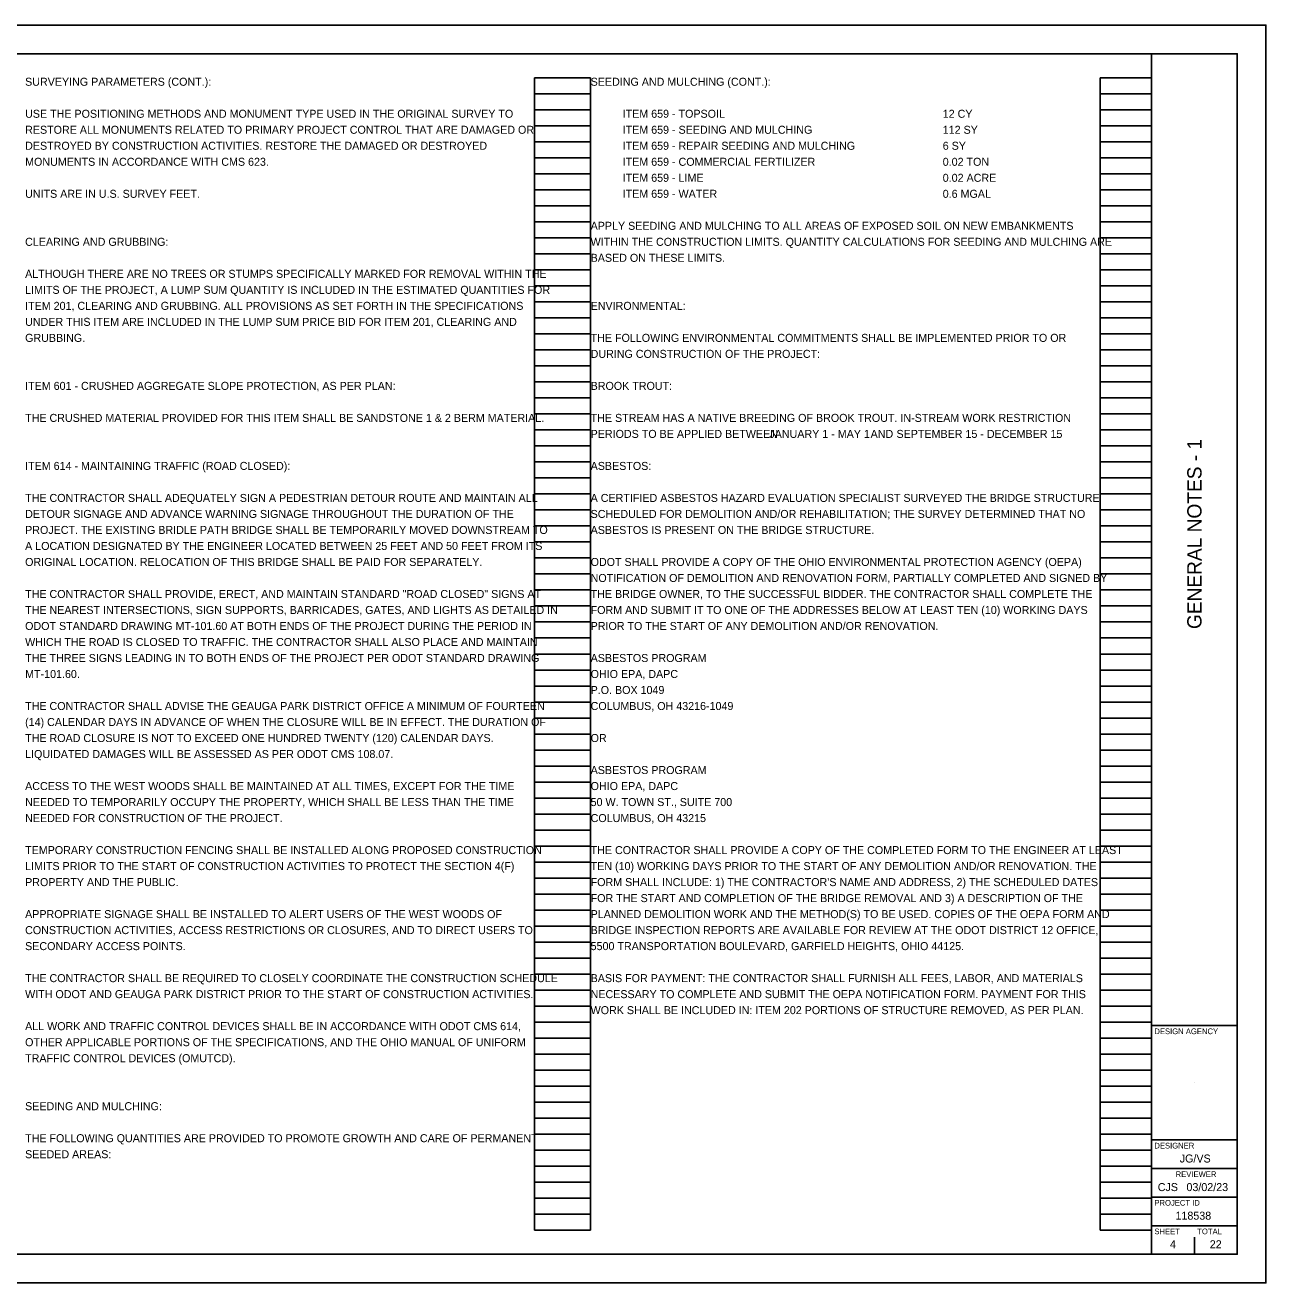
# Model space of a CAD drawing. Extents: x 0 to 34, y -0.1 to 22.
# Drawn here: x 12.29 to 34, y 0 to 22 of the extents above; entities that cross this region are included whole.
import ezdxf

# ---------------------------------------------------------------- set-up
doc = ezdxf.new("R2010")
doc.units = 0
for name, color, linetype in [('SH_Border', 7, 'Continuous'), ('SH_Cut_Line', 7, 'Continuous'), ('SH_Data', 7, 'Continuous'), ('SH_Text', 7, 'Continuous')]:
    doc.layers.add(name, color=color, linetype=linetype)

msp = doc.modelspace()

# ---------------------------------------------------------------- linework, layer by layer
at = {"layer": 'SH_Border'}
for p, q in [((32, 0.5), (32, 21.5)), ((32, 4.5), (33.5, 4.5)), ((32, 2.5), (33.5, 2.5)), ((32, 2), (33.5, 2)), ((32, 1.5), (33.5, 1.5)), ((32, 1), (33.5, 1))]:
    msp.add_line(p, q, dxfattribs=at)
msp.add_lwpolyline([(1.5, 21.5), (33.5, 21.5), (33.5, 0.5), (1.5, 0.5)], close=True, dxfattribs=at)
at = {"layer": 'SH_Cut_Line'}
msp.add_lwpolyline([(0, 0), (34, 0), (34, 22), (0, 22)], close=True, dxfattribs=at)
at = {"layer": 'SH_Data'}
for p, q in [((21.207, 0.92), (21.207, 21.08)), ((21.207, 21.08), (22.187, 21.08)), ((22.187, 0.92), (22.187, 21.08)), ((31.1, 0.92), (31.1, 21.08)), ((31.1, 21.08), (32, 21.08)), ((32, 0.92), (32, 21.08)), ((21.207, 20.8), (22.187, 20.8)), ((31.1, 20.8), (32, 20.8)), ((21.207, 20.52), (22.187, 20.52)), ((31.1, 20.52), (32, 20.52)), ((21.207, 20.24), (22.187, 20.24)), ((31.1, 20.24), (32, 20.24)), ((21.207, 19.96), (22.187, 19.96)), ((31.1, 19.96), (32, 19.96)), ((21.207, 19.68), (22.187, 19.68)), ((31.1, 19.68), (32, 19.68)), ((21.207, 19.4), (22.187, 19.4)), ((31.1, 19.4), (32, 19.4)), ((21.207, 19.12), (22.187, 19.12)), ((31.1, 19.12), (32, 19.12)), ((21.207, 18.84), (22.187, 18.84)), ((31.1, 18.84), (32, 18.84)), ((21.207, 18.56), (22.187, 18.56)), ((31.1, 18.56), (32, 18.56)), ((21.207, 18.28), (22.187, 18.28)), ((31.1, 18.28), (32, 18.28)), ((21.207, 18), (22.187, 18)), ((31.1, 18), (32, 18)), ((21.207, 17.72), (22.187, 17.72)), ((31.1, 17.72), (32, 17.72)), ((21.207, 17.44), (22.187, 17.44)), ((31.1, 17.44), (32, 17.44)), ((21.207, 17.16), (22.187, 17.16)), ((31.1, 17.16), (32, 17.16)), ((21.207, 16.88), (22.187, 16.88)), ((31.1, 16.88), (32, 16.88)), ((21.207, 16.6), (22.187, 16.6)), ((31.1, 16.6), (32, 16.6)), ((21.207, 16.32), (22.187, 16.32)), ((31.1, 16.32), (32, 16.32)), ((21.207, 16.04), (22.187, 16.04)), ((31.1, 16.04), (32, 16.04)), ((21.207, 15.76), (22.187, 15.76)), ((31.1, 15.76), (32, 15.76)), ((21.207, 15.48), (22.187, 15.48)), ((31.1, 15.48), (32, 15.48)), ((21.207, 15.2), (22.187, 15.2)), ((31.1, 15.2), (32, 15.2)), ((21.207, 14.92), (22.187, 14.92)), ((31.1, 14.92), (32, 14.92)), ((21.207, 14.64), (22.187, 14.64)), ((31.1, 14.64), (32, 14.64)), ((21.207, 14.36), (22.187, 14.36)), ((31.1, 14.36), (32, 14.36)), ((21.207, 14.08), (22.187, 14.08)), ((31.1, 14.08), (32, 14.08)), ((21.207, 13.8), (22.187, 13.8)), ((31.1, 13.8), (32, 13.8)), ((21.207, 13.52), (22.187, 13.52)), ((31.1, 13.52), (32, 13.52)), ((21.207, 13.24), (22.187, 13.24)), ((31.1, 13.24), (32, 13.24)), ((21.207, 12.96), (22.187, 12.96)), ((31.1, 12.96), (32, 12.96)), ((21.207, 12.68), (22.187, 12.68)), ((31.1, 12.68), (32, 12.68)), ((21.207, 12.4), (22.187, 12.4)), ((31.1, 12.4), (32, 12.4)), ((21.207, 12.12), (22.187, 12.12)), ((31.1, 12.12), (32, 12.12)), ((21.207, 11.84), (22.187, 11.84)), ((31.1, 11.84), (32, 11.84)), ((21.207, 11.56), (22.187, 11.56)), ((31.1, 11.56), (32, 11.56)), ((21.207, 11.28), (22.187, 11.28)), ((31.1, 11.28), (32, 11.28)), ((21.207, 11), (22.187, 11)), ((31.1, 11), (32, 11)), ((21.207, 10.72), (22.187, 10.72)), ((31.1, 10.72), (32, 10.72)), ((21.207, 10.44), (22.187, 10.44)), ((31.1, 10.44), (32, 10.44)), ((21.207, 10.16), (22.187, 10.16)), ((31.1, 10.16), (32, 10.16)), ((21.207, 9.88), (22.187, 9.88)), ((31.1, 9.88), (32, 9.88)), ((21.207, 9.6), (22.187, 9.6)), ((31.1, 9.6), (32, 9.6)), ((21.207, 9.32), (22.187, 9.32)), ((31.1, 9.32), (32, 9.32)), ((21.207, 9.04), (22.187, 9.04)), ((31.1, 9.04), (32, 9.04)), ((21.207, 8.76), (22.187, 8.76)), ((31.1, 8.76), (32, 8.76)), ((21.207, 8.48), (22.187, 8.48)), ((31.1, 8.48), (32, 8.48)), ((21.207, 8.2), (22.187, 8.2)), ((31.1, 8.2), (32, 8.2)), ((21.207, 7.92), (22.187, 7.92)), ((31.1, 7.92), (32, 7.92)), ((21.207, 7.64), (22.187, 7.64)), ((31.1, 7.64), (32, 7.64)), ((21.207, 7.36), (22.187, 7.36)), ((31.1, 7.36), (32, 7.36)), ((21.207, 7.08), (22.187, 7.08)), ((31.1, 7.08), (32, 7.08)), ((21.207, 6.8), (22.187, 6.8)), ((31.1, 6.8), (32, 6.8)), ((21.207, 6.52), (22.187, 6.52)), ((31.1, 6.52), (32, 6.52)), ((21.207, 6.24), (22.187, 6.24)), ((31.1, 6.24), (32, 6.24)), ((21.207, 5.96), (22.187, 5.96)), ((31.1, 5.96), (32, 5.96)), ((21.207, 5.68), (22.187, 5.68)), ((31.1, 5.68), (32, 5.68)), ((21.207, 5.4), (22.187, 5.4)), ((31.1, 5.4), (32, 5.4)), ((21.207, 5.12), (22.187, 5.12)), ((31.1, 5.12), (32, 5.12)), ((21.207, 4.84), (22.187, 4.84)), ((31.1, 4.84), (32, 4.84)), ((21.207, 4.56), (22.187, 4.56)), ((31.1, 4.56), (32, 4.56)), ((21.207, 4.28), (22.187, 4.28)), ((31.1, 4.28), (32, 4.28)), ((21.207, 4), (22.187, 4)), ((31.1, 4), (32, 4)), ((21.207, 3.72), (22.187, 3.72)), ((31.1, 3.72), (32, 3.72)), ((21.207, 3.44), (22.187, 3.44)), ((31.1, 3.44), (32, 3.44)), ((32.75, 3.5), (32.75, 3.5)), ((21.207, 3.16), (22.187, 3.16)), ((31.1, 3.16), (32, 3.16)), ((21.207, 2.88), (22.187, 2.88)), ((31.1, 2.88), (32, 2.88)), ((21.207, 2.6), (22.187, 2.6)), ((31.1, 2.6), (32, 2.6)), ((21.207, 2.32), (22.187, 2.32)), ((31.1, 2.32), (32, 2.32)), ((21.207, 2.04), (22.187, 2.04)), ((31.1, 2.04), (32, 2.04)), ((21.207, 1.76), (22.187, 1.76)), ((31.1, 1.76), (32, 1.76)), ((21.207, 1.48), (22.187, 1.48)), ((31.1, 1.48), (32, 1.48)), ((21.207, 1.2), (22.187, 1.2)), ((31.1, 1.2), (32, 1.2)), ((21.207, 0.92), (22.187, 0.92)), ((31.1, 0.92), (32, 0.92)), ((32.375, 0.675), (32.375, 0.675)), ((32.75, 0.5), (32.75, 0.8))]:
    msp.add_line(p, q, dxfattribs=at)

# ---------------------------------------------------------------- texts
msp.add_text('GENERAL NOTES - 1', height=0.25, rotation=90, dxfattribs=at).set_placement((32.875, 11.437))
for s, height, p in [('DESIGN AGENCY', 0.1, (32.05, 4.35)), ('DESIGNER', 0.1, (32.05, 2.35)), ('JG/VS', 0.14, (32.494, 2.105)), ('REVIEWER', 0.1, (32.422, 1.85)), ('CJS', 0.14, (32.109, 1.605)), ('03/02/23', 0.14, (32.611, 1.605)), ('PROJECT ID', 0.1, (32.05, 1.35)), ('118538', 0.14, (32.419, 1.105)), ('SHEET', 0.1, (32.05, 0.85)), ('TOTAL', 0.1, (32.8, 0.85)), ('4', 0.14, (32.322, 0.605)), ('22', 0.14, (33.019, 0.605))]:
    msp.add_text(s, height=height, dxfattribs=at).set_placement(p)
at = {"layer": 'SH_Text'}
for s, p in [('SURVEYING PARAMETERS (CONT.):', (12.293, 20.94)), ('SEEDING AND MULCHING (CONT.):', (22.187, 20.94)), ('USE THE POSITIONING METHODS AND MONUMENT TYPE USED IN THE ORIGINAL SURVEY TO ', (12.293, 20.38)), ('ITEM 659 - TOPSOIL', (22.747, 20.38)), ('12 CY', (28.347, 20.38)), ('RESTORE ALL MONUMENTS RELATED TO PRIMARY PROJECT CONTROL THAT ARE DAMAGED OR', (12.293, 20.1)), ('ITEM 659 - SEEDING AND MULCHING', (22.747, 20.1)), ('112 SY', (28.347, 20.1)), ('DESTROYED BY CONSTRUCTION ACTIVITIES. RESTORE THE DAMAGED OR DESTROYED ', (12.293, 19.82)), ('ITEM 659 - REPAIR SEEDING AND MULCHING', (22.747, 19.82)), ('6 SY', (28.347, 19.82)), ('MONUMENTS IN ACCORDANCE WITH CMS 623.', (12.293, 19.54)), ('ITEM 659 - COMMERCIAL FERTILIZER', (22.747, 19.54)), ('0.02 TON', (28.347, 19.54)), ('ITEM 659 - LIME', (22.747, 19.26)), ('0.02 ACRE', (28.347, 19.26)), ('UNITS ARE IN U.S. SURVEY FEET.', (12.293, 18.98)), ('ITEM 659 - WATER', (22.747, 18.98)), ('0.6 MGAL', (28.347, 18.98)), ('APPLY SEEDING AND MULCHING TO ALL AREAS OF EXPOSED SOIL ON NEW EMBANKMENTS ', (22.187, 18.42)), ('CLEARING AND GRUBBING:', (12.293, 18.14)), ('WITHIN THE CONSTRUCTION LIMITS. QUANTITY CALCULATIONS FOR SEEDING AND MULCHING ARE ', (22.187, 18.14)), ('BASED ON THESE LIMITS.', (22.187, 17.86)), ('ALTHOUGH THERE ARE NO TREES OR STUMPS SPECIFICALLY MARKED FOR REMOVAL WITHIN THE ', (12.293, 17.58)), ('LIMITS OF THE PROJECT, A LUMP SUM QUANTITY IS INCLUDED IN THE ESTIMATED QUANTITIES FOR ', (12.293, 17.3)), ('ITEM 201, CLEARING AND GRUBBING. ALL PROVISIONS AS SET FORTH IN THE SPECIFICATIONS ', (12.293, 17.02)), ('ENVIRONMENTAL:', (22.187, 17.02)), ('UNDER THIS ITEM ARE INCLUDED IN THE LUMP SUM PRICE BID FOR ITEM 201, CLEARING AND ', (12.293, 16.74)), ('GRUBBING.', (12.293, 16.46)), ('THE FOLLOWING ENVIRONMENTAL COMMITMENTS SHALL BE IMPLEMENTED PRIOR TO OR ', (22.187, 16.46)), ('DURING CONSTRUCTION OF THE PROJECT:', (22.187, 16.18)), ('ITEM 601 - CRUSHED AGGREGATE SLOPE PROTECTION, AS PER PLAN:', (12.293, 15.62)), ('BROOK TROUT:', (22.187, 15.62)), ('THE CRUSHED MATERIAL PROVIDED FOR THIS ITEM SHALL BE SANDSTONE 1 & 2 BERM MATERIAL.', (12.293, 15.06)), ('THE STREAM HAS A NATIVE BREEDING OF BROOK TROUT. IN-STREAM WORK RESTRICTION ', (22.187, 15.06)), ('PERIODS TO BE APPLIED BETWEEN ', (22.187, 14.78)), ('JANUARY 1 - MAY 1', (25.314, 14.78)), (' AND ', (27.033, 14.78)), ('SEPTEMBER 15 - DECEMBER 15', (27.538, 14.78)), ('.', (30.322, 14.78)), ('ITEM 614 - MAINTAINING TRAFFIC (ROAD CLOSED):', (12.293, 14.22)), ('ASBESTOS:', (22.187, 14.22)), ('THE CONTRACTOR SHALL ADEQUATELY SIGN A PEDESTRIAN DETOUR ROUTE AND MAINTAIN ALL ', (12.293, 13.66)), ('A CERTIFIED ASBESTOS HAZARD EVALUATION SPECIALIST SURVEYED THE BRIDGE STRUCTURE ', (22.187, 13.66)), ('DETOUR SIGNAGE AND ADVANCE WARNING SIGNAGE THROUGHOUT THE DURATION OF THE ', (12.293, 13.38)), ('SCHEDULED FOR DEMOLITION AND/OR REHABILITATION; THE SURVEY DETERMINED THAT NO ', (22.187, 13.38)), ('PROJECT. THE EXISTING BRIDLE PATH BRIDGE SHALL BE TEMPORARILY MOVED DOWNSTREAM TO ', (12.293, 13.1)), ('ASBESTOS IS PRESENT ON THE BRIDGE STRUCTURE.', (22.187, 13.1)), ('A LOCATION DESIGNATED BY THE ENGINEER LOCATED BETWEEN 25 FEET AND 50 FEET FROM ITS ', (12.293, 12.82)), ('ORIGINAL LOCATION. RELOCATION OF THIS BRIDGE SHALL BE PAID FOR SEPARATELY.', (12.293, 12.54)), ('ODOT SHALL PROVIDE A COPY OF THE OHIO ENVIRONMENTAL PROTECTION AGENCY (OEPA) ', (22.187, 12.54)), ('NOTIFICATION OF DEMOLITION AND RENOVATION FORM, PARTIALLY COMPLETED AND SIGNED BY ', (22.187, 12.26)), ('THE CONTRACTOR SHALL PROVIDE, ERECT, AND MAINTAIN STANDARD "ROAD CLOSED" SIGNS AT ', (12.293, 11.98)), ('THE BRIDGE OWNER, TO THE SUCCESSFUL BIDDER. THE CONTRACTOR SHALL COMPLETE THE ', (22.187, 11.98)), ('THE NEAREST INTERSECTIONS, SIGN SUPPORTS, BARRICADES, GATES, AND LIGHTS AS DETAILED IN ', (12.293, 11.7)), ('FORM AND SUBMIT IT TO ONE OF THE ADDRESSES BELOW AT LEAST TEN (10) WORKING DAYS ', (22.187, 11.7)), ('ODOT STANDARD DRAWING MT-101.60 AT BOTH ENDS OF THE PROJECT DURING THE PERIOD IN ', (12.293, 11.42)), ('PRIOR TO THE START OF ANY DEMOLITION AND/OR RENOVATION.', (22.187, 11.42)), ('WHICH THE ROAD IS CLOSED TO TRAFFIC. THE CONTRACTOR SHALL ALSO PLACE AND MAINTAIN ', (12.293, 11.14)), ('THE THREE SIGNS LEADING IN TO BOTH ENDS OF THE PROJECT PER ODOT STANDARD DRAWING ', (12.293, 10.86)), ('ASBESTOS PROGRAM', (22.187, 10.86)), ('MT-101.60.', (12.293, 10.58)), ('OHIO EPA, DAPC', (22.187, 10.58)), ('P.O. BOX 1049', (22.187, 10.3)), ('THE CONTRACTOR SHALL ADVISE THE GEAUGA PARK DISTRICT OFFICE A MINIMUM OF FOURTEEN ', (12.293, 10.02)), ('COLUMBUS, OH 43216-1049', (22.187, 10.02)), ('(14) CALENDAR DAYS IN ADVANCE OF WHEN THE CLOSURE WILL BE IN EFFECT. THE DURATION OF ', (12.293, 9.74)), ('THE ROAD CLOSURE IS NOT TO EXCEED ONE HUNDRED TWENTY (120) CALENDAR DAYS. ', (12.293, 9.46)), ('OR', (22.187, 9.46)), ('LIQUIDATED DAMAGES WILL BE ASSESSED AS PER ODOT CMS 108.07.', (12.293, 9.18)), ('ASBESTOS PROGRAM', (22.187, 8.9)), ('ACCESS TO THE WEST WOODS SHALL BE MAINTAINED AT ALL TIMES, EXCEPT FOR THE TIME ', (12.293, 8.62)), ('OHIO EPA, DAPC', (22.187, 8.62)), ('NEEDED TO TEMPORARILY OCCUPY THE PROPERTY, WHICH SHALL BE LESS THAN THE TIME ', (12.293, 8.34)), ('50 W. TOWN ST., SUITE 700', (22.187, 8.34)), ('NEEDED FOR CONSTRUCTION OF THE PROJECT.', (12.293, 8.06)), ('COLUMBUS, OH 43215', (22.187, 8.06)), ('TEMPORARY CONSTRUCTION FENCING SHALL BE INSTALLED ALONG PROPOSED CONSTRUCTION ', (12.293, 7.5)), ('THE CONTRACTOR SHALL PROVIDE A COPY OF THE COMPLETED FORM TO THE ENGINEER AT LEAST ', (22.187, 7.5)), ('LIMITS PRIOR TO THE START OF CONSTRUCTION ACTIVITIES TO PROTECT THE SECTION 4(F) ', (12.293, 7.22)), ('TEN (10) WORKING DAYS PRIOR TO THE START OF ANY DEMOLITION AND/OR RENOVATION. THE ', (22.187, 7.22)), ('PROPERTY AND THE PUBLIC.', (12.293, 6.94)), ("FORM SHALL INCLUDE: 1) THE CONTRACTOR'S NAME AND ADDRESS, 2) THE SCHEDULED DATES ", (22.187, 6.94)), ('FOR THE START AND COMPLETION OF THE BRIDGE REMOVAL AND 3) A DESCRIPTION OF THE ', (22.187, 6.66)), ('APPROPRIATE SIGNAGE SHALL BE INSTALLED TO ALERT USERS OF THE WEST WOODS OF ', (12.293, 6.38)), ('PLANNED DEMOLITION WORK AND THE METHOD(S) TO BE USED. COPIES OF THE OEPA FORM AND ', (22.187, 6.38)), ('CONSTRUCTION ACTIVITIES, ACCESS RESTRICTIONS OR CLOSURES, AND TO DIRECT USERS TO ', (12.293, 6.1)), ('BRIDGE INSPECTION REPORTS ARE AVAILABLE FOR REVIEW AT THE ODOT DISTRICT 12 OFFICE, ', (22.187, 6.1)), ('SECONDARY ACCESS POINTS.', (12.293, 5.82)), ('5500 TRANSPORTATION BOULEVARD, GARFIELD HEIGHTS, OHIO 44125.', (22.187, 5.82)), ('THE CONTRACTOR SHALL BE REQUIRED TO CLOSELY COORDINATE THE CONSTRUCTION SCHEDULE ', (12.293, 5.26)), ('BASIS FOR PAYMENT: THE CONTRACTOR SHALL FURNISH ALL FEES, LABOR, AND MATERIALS ', (22.187, 5.26)), ('WITH ODOT AND GEAUGA PARK DISTRICT PRIOR TO THE START OF CONSTRUCTION ACTIVITIES.', (12.293, 4.98)), ('NECESSARY TO COMPLETE AND SUBMIT THE OEPA NOTIFICATION FORM. PAYMENT FOR THIS ', (22.187, 4.98)), ('WORK SHALL BE INCLUDED IN: ITEM 202 PORTIONS OF STRUCTURE REMOVED, AS PER PLAN.', (22.187, 4.7)), ('ALL WORK AND TRAFFIC CONTROL DEVICES SHALL BE IN ACCORDANCE WITH ODOT CMS 614, ', (12.293, 4.42)), ('OTHER APPLICABLE PORTIONS OF THE SPECIFICATIONS, AND THE OHIO MANUAL OF UNIFORM ', (12.293, 4.14)), ('TRAFFIC CONTROL DEVICES (OMUTCD).', (12.293, 3.86)), ('SEEDING AND MULCHING:', (12.293, 3.02)), ('THE FOLLOWING QUANTITIES ARE PROVIDED TO PROMOTE GROWTH AND CARE OF PERMANENT ', (12.293, 2.46)), ('SEEDED AREAS:', (12.293, 2.18))]:
    msp.add_text(s, height=0.14, dxfattribs=at).set_placement(p)

doc.saveas('drawing.dxf')
